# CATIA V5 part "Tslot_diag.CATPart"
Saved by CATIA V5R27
Part number: Tslot_diag
Bounding box of the stored display mesh (mm): x -19.056 to 19.056, y -19.056 to 19.056, z -1318.68 to -638
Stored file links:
  \\triton.meca.polymtl.ca\usagers\zaoue\profiles\Desktop\varm_ass\structure prismatique\Tslot_diag.CATPart
  \\triton.meca.polymtl.ca\usagers\zaoue\profiles\Desktop\Clean_varm_CAD-20230123T141814Z-001\Clean_varm_CAD\Alu_Tslot_44in.CATPart
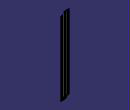
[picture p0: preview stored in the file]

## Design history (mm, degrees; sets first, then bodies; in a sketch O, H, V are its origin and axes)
Body1 (main body)
Body2 "Boss-Extrude1"
  Solid1: solid without history
  Sketch1 on face of Solid1, origin (0, 0, 1524), H (1, 0, 0), V (0, 1, 0)
    line L1 (-31.855, 32.792) -> (28.107, 32.792)
    line L2 (28.107, 32.792) -> (28.107, -28.509)
    line L3 (28.107, -28.509) -> (-31.855, -28.509)
    line L4 (-31.855, -28.509) -> (-31.855, 32.792)
    horizontal: L1 H, L3 H
    vertical: L2 V, L4 V
    fix: L1, L2, L3, L4
  Pocket1: profile Sketch1, direction (0, 0, -1), length 2162
  Sketch2 on end face of Pocket1, origin (0, 0, -638), H (1, 0, 0), V (0, 1, 0)
    line L1 (19.05, -7.9756) -> (19.05, -9.4996)
    arc A1 centre (19.05, -8.7376) radius 0.762 from (19.05, -7.9756) to (19.05, -9.4996) ccw
    point P3 (19.05, -8.7376)
    reference projected arc E1 centre (19.05, -8.7376) radius 0.762 from (19.05, -7.9756) to (18.288, -8.7376) ccw from edge [end face of Pocket1 | face of Solid1]
    reference projected arc E2 centre (19.05, -8.7376) radius 0.762 from (19.05, -7.9756) to (18.288, -8.7376) ccw from edge [end face of Pocket1 | face of Solid1]
    reference projected arc E3 centre (19.05, -8.7376) radius 0.762 from (19.05, -7.9756) to (18.288, -8.7376) ccw from edge [end face of Pocket1 | face of Solid1]
    line L2 (19.0564, 15.8623) -> (19.0564, 14.3256)
    point P4 (19.0564, 15.0939)
    arc A2 centre (19.0564, 15.0939) radius 0.7684 from (19.0564, 15.8623) to (19.0564, 14.3256) ccw
    line L3 (19.0564, -14.3256) -> (19.0564, -15.8623)
    point P7 (19.0564, -15.0939)
    line L4 (19.05, 9.4996) -> (19.05, 7.9756)
    point P8 (19.05, 8.7376)
    arc A3 centre (19.0564, -15.0939) radius 0.7684 from (19.0564, -14.3256) to (19.0564, -15.8623) ccw
    arc A4 centre (19.05, 8.7376) radius 0.762 from (19.05, 9.4996) to (19.05, 7.9756) ccw
    reference projected arc E4 centre (19.0564, -15.0939) radius 0.7684 from (19.05, -14.3256) to (18.288, -15.0939) ccw from edge [end face of Pocket1 | face of Solid1]
    reference projected arc E5 centre (19.0564, -15.0939) radius 0.7684 from (19.05, -14.3256) to (18.288, -15.0939) ccw from edge [end face of Pocket1 | face of Solid1]
    reference projected arc E6 centre (19.05, 8.7376) radius 0.762 from (19.05, 9.4996) to (18.288, 8.7376) ccw from edge [end face of Pocket1 | face of Solid1]
    reference projected arc E7 centre (19.05, 8.7376) radius 0.762 from (19.05, 9.4996) to (18.288, 8.7376) ccw from edge [end face of Pocket1 | face of Solid1]
    reference projected arc E8 centre (19.0564, 15.0939) radius 0.7684 from (19.05, 15.8623) to (18.288, 15.0939) ccw from edge [end face of Pocket1 | face of Solid1]
    reference projected arc E9 centre (19.0564, 15.0939) radius 0.7684 from (19.05, 15.8623) to (18.288, 15.0939) ccw from edge [end face of Pocket1 | face of Solid1]
    line L5 (14.3256, -19.0563) -> (15.8623, -19.0563)
    arc A5 centre (15.0939, -19.0563) radius 0.7684 from (15.8623, -19.0563) to (14.3256, -19.0563) ccw
    point P15 (15.0939, -19.0563)
    line L6 (-15.8623, -19.0563) -> (-14.3256, -19.0563)
    point P16 (-15.0939, -19.0563)
    arc A6 centre (-15.0939, -19.0563) radius 0.7684 from (-14.3256, -19.0563) to (-15.8623, -19.0563) ccw
    line L7 (7.9756, -19.05) -> (9.4996, -19.05)
    point P19 (8.7376, -19.05)
    arc A7 centre (8.7376, -19.05) radius 0.762 from (9.4996, -19.05) to (7.9756, -19.05) ccw
    line L8 (-9.4996, -19.05) -> (-7.9756, -19.05)
    point P22 (-8.7376, -19.05)
    arc A8 centre (-8.7376, -19.05) radius 0.762 from (-7.9756, -19.05) to (-9.4996, -19.05) ccw
    reference projected arc E10 centre (-15.0939, -19.0563) radius 0.7684 from (-14.3256, -19.05) to (-15.8623, -19.05) ccw from edge [end face of Pocket1 | face of Solid1]
    reference projected arc E11 centre (-15.0939, -19.0563) radius 0.7684 from (-14.3256, -19.05) to (-15.8623, -19.05) ccw from edge [end face of Pocket1 | face of Solid1]
    reference projected arc E12 centre (15.0939, -19.0563) radius 0.7684 from (15.8623, -19.05) to (14.3256, -19.05) ccw from edge [end face of Pocket1 | face of Solid1]
    reference projected arc E13 centre (15.0939, -19.0563) radius 0.7684 from (15.8623, -19.05) to (14.3256, -19.05) ccw from edge [end face of Pocket1 | face of Solid1]
    reference projected arc E14 centre (15.0939, -19.0563) radius 0.7684 from (15.8623, -19.05) to (14.3256, -19.05) ccw from edge [end face of Pocket1 | face of Solid1]
    reference projected arc E15 centre (8.7376, -19.05) radius 0.762 from (9.4996, -19.05) to (7.9756, -19.05) ccw from edge [end face of Pocket1 | face of Solid1]
    reference projected arc E16 centre (8.7376, -19.05) radius 0.762 from (9.4996, -19.05) to (7.9756, -19.05) ccw from edge [end face of Pocket1 | face of Solid1]
    reference projected arc E17 centre (-8.7376, -19.05) radius 0.762 from (-7.9756, -19.05) to (-9.4996, -19.05) ccw from edge [end face of Pocket1 | face of Solid1]
    reference projected arc E18 centre (-8.7376, -19.05) radius 0.762 from (-7.9756, -19.05) to (-9.4996, -19.05) ccw from edge [end face of Pocket1 | face of Solid1]
    construction line L9 (0, 0) -> (35.726, 0)
    construction line L10 (0, 0) -> (0, -21.547)
    radius A1 = 0.762
    radius E3 = 0.762 (reference)
    vertical: L1 V, L2 V, L3 V, L4 V, L10 V
    midpoint: P3 L1, P4 L2, P7 L3, P8 L4, P15 L5, P16 L6, P19 L7, P22 L8
    coincidence: A1 E1, A3 E4, A4 E6, A2 E8, A6 E10, A5 E14, A7 E15, A8 E17
    concentricity: A1 E2, A3 E5, A4 E7, A2 E9, A6 E11, A5 E12, A5 E13, A7 E16, A8 E18
    horizontal: L5 H, L6 H, L7 H, L8 H, L9 H
  Pad1: profile Sketch2, direction (0, 0, -1), up to face of Solid1
  Mirror1: of Pad1, about {plane type Offset, RefPlane face of Solid1, Offset 19.05}
  Mirror2: of Pad1, about {plane type Offset, RefPlane face of Solid1, Offset 19.05}
  Sketch3 on face of Solid1, origin (19.05, -9.4996, 1524), H (0, -1, 0), V (0, 0, 1)
    line L1 (-28.5559, -2162) -> (16.4441, -2162)
    point P1 (-28.5559, -2162)
    line L2 (-28.5559, -2162) -> (16.4441, -2239.9423)
    line L3 (16.4441, -2239.9423) -> (16.4441, -2162)
    reference projected line E1 (-1.524, -2162) -> (-3.8608, -2162) from edge [face of Pocket1 | face of Solid1]
    reference projected line E3 (-28.5559, -2162) -> (-28.5559, -3048) from edge [face of Mirror2 | face of Mirror2]
    angle L3 L2 = 30
    length L1 = 45
    horizontal: L1 H
    vertical: L3 V
    coincidence: L1 E1, P1 E3
  Pocket2: profile Sketch3, direction (-1, 0, 0), through (limit type 3), opposite side through (limit type 3)
  DatumCurve1
  Sketch4 on face of Solid1, origin (19.05, -9.4996, 1524), H (0, -1, 0), V (0, 0, 1)
    line L1 (16.7308, -2855.1063) -> (-37.5518, -2761.086)
    point P1 (16.7308, -2855.1063)
    line L2 (-37.5518, -2761.086) -> (-37.5518, -3068.953)
    line L3 (-37.5518, -3068.953) -> (16.7308, -3068.953)
    line L4 (16.7308, -3068.953) -> (16.7308, -2855.1063)
    point P5 (16.7308, -2855.1063)
    reference projected line E1 (206.1802, -3183.2422) -> (-353.8198, -2213.2937) from edge of DatumCurve1
    vertical: L2 V, L4 V
    horizontal: L3 H
    coincidence: P5 L1, P1 P5, L1 E1
    fix: L2, L3, L4
  Pocket3: profile Sketch4, direction (-1, 0, 0), through (limit type 3), opposite side through (limit type 3)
